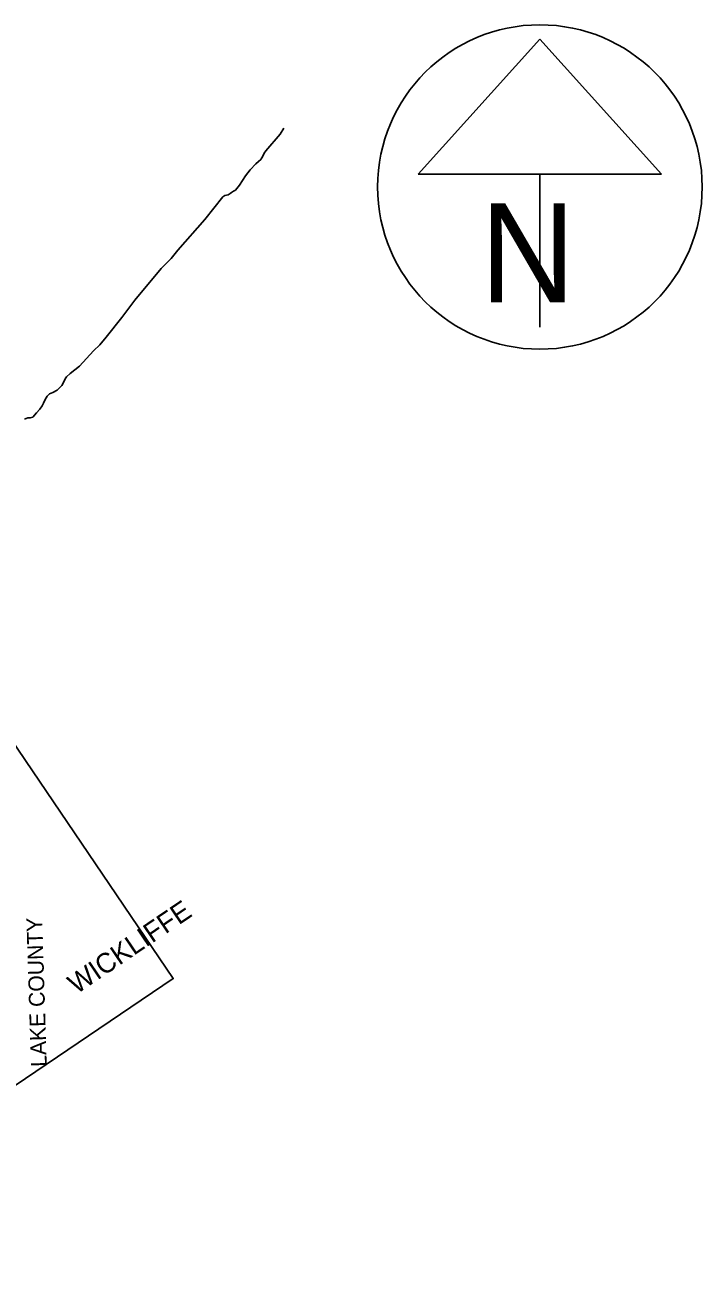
# Model space of a CAD drawing. Extents: x 2139079 to 2262683, y 1235796 to 1334992.
# Drawn here: x 2245568 to 2262683, y 1303635 to 1334992 of the extents above; entities that cross this region are included whole.
import ezdxf

# ---------------------------------------------------------------- set-up
doc = ezdxf.new("R2010")
doc.units = 0
for name, color, linetype in [('GM_X_Adjacent_County', 7, 'Continuous'), ('GM_X_Adjacent_County_Text', 7, 'Continuous'), ('GM_X_State_Route', 7, 'Continuous'), ('GM_X_US_Route', 7, 'Continuous'), ('SH_Masking', 7, 'Continuous'), ('SH_Text', 7, 'Continuous')]:
    doc.layers.add(name, color=color, linetype=linetype)

msp = doc.modelspace()

# ---------------------------------------------------------------- linework, layer by layer
at = {"layer": 'GM_X_Adjacent_County'}
msp.add_lwpolyline([(2245556, 1325020), (2245646, 1325055), (2245704, 1325056), (2245769, 1325074), (2245864, 1325181), (2245943, 1325275), (2246007, 1325360), (2246041, 1325430), (2246082, 1325518), (2246131, 1325602), (2246194, 1325663), (2246277, 1325695), (2246388, 1325756), (2246499, 1325873), (2246561, 1325979), (2246583, 1326039), (2246618, 1326095), (2246715, 1326178), (2246948, 1326364), (2247299, 1326752), (2247467, 1326905), (2247626, 1327094), (2248018, 1327592), (2248346, 1328034), (2249010, 1328830), (2249264, 1329080), (2249432, 1329297), (2250119, 1330067), (2250568, 1330640), (2250623, 1330676), (2250667, 1330685), (2250709, 1330693), (2250755, 1330724), (2250786, 1330752), (2250840, 1330784), (2250895, 1330815), (2250988, 1330935), (2251072, 1331054), (2251143, 1331174), (2251259, 1331325), (2251401, 1331479), (2251476, 1331538), (2251529, 1331586), (2251580, 1331669), (2251613, 1331743), (2251658, 1331805), (2252019, 1332231), (2252112, 1332379)], dxfattribs=at)
at = {"layer": 'GM_X_US_Route'}
msp.add_lwpolyline([(2202868, 1295541), (2210354, 1284489), (2249318, 1310882), (2241832, 1321934)], close=True, dxfattribs=at)
at = {"layer": 'SH_Masking'}
msp.add_circle((2258583, 1330892), 4100, dxfattribs=at)
at = {"layer": 'SH_Text'}
for p, q in [((2258583, 1334629), (2255507, 1331217)), ((2261659, 1331217), (2258583, 1334629)), ((2255507, 1331217), (2261659, 1331217)), ((2258583, 1331217), (2258583, 1327349))]:
    msp.add_line(p, q, dxfattribs=at)
msp.add_circle((2258583, 1330892), 4100, dxfattribs=at)

# ---------------------------------------------------------------- texts
at = {"layer": 'GM_X_Adjacent_County_Text'}
msp.add_text('LAKE COUNTY', height=400, rotation=91.764, dxfattribs=at).set_placement((2246123, 1308654))
at = {"layer": 'GM_X_State_Route'}
msp.add_text('WICKLIFFE', height=500, rotation=34.1113, dxfattribs=at).set_placement((2246875, 1310475))
at = {"layer": 'SH_Text'}
msp.add_text('N', height=2500, dxfattribs=at).set_placement((2257070, 1327979))

doc.saveas('drawing.dxf')
